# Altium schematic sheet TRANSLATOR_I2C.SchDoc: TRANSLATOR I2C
size A4; Author: Silvio Navaretti; CompanyName: ARDUINO SRL; DrawnBy: Silvio Navaretti; Engineer: Silvio Navaretti; Organization: ARDUINO SRL; DocumentNumber: ASX00083; SheetNumber: 4; SheetTotal: 11; RevAuthor: Silvio Navaretti
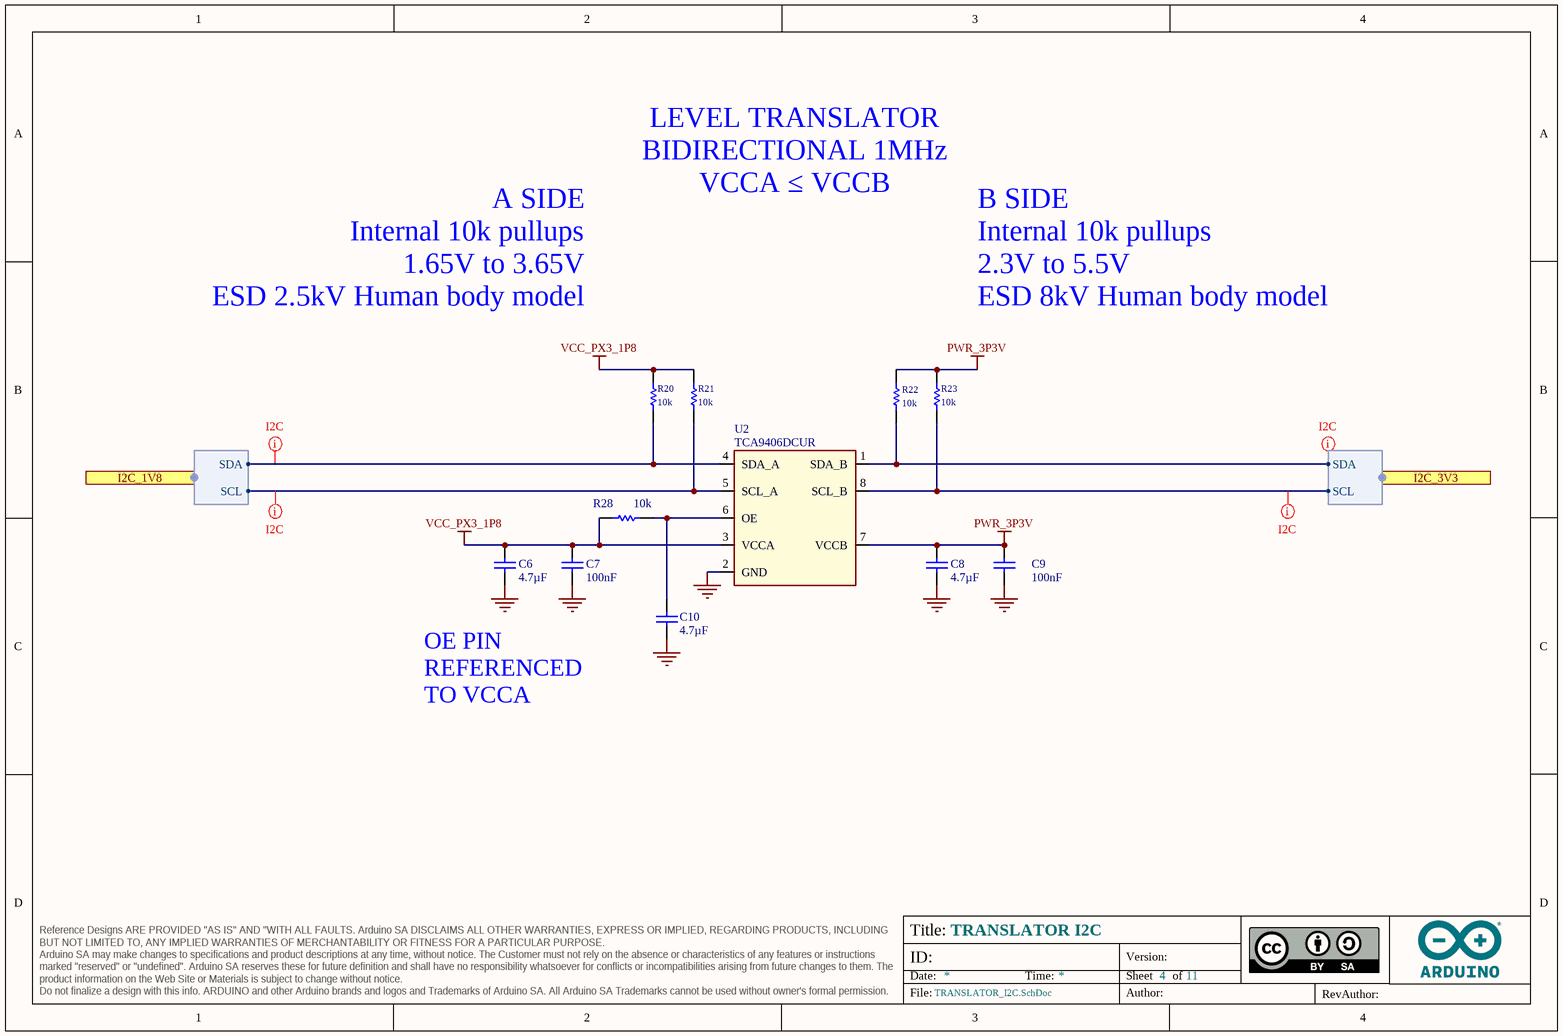
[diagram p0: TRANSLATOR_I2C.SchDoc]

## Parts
C6  value 4.7µF  [CAP-0402]  (hidden comment: C1005A475M6R3NT)
C7  value 100nF  [CAP-0402]  (hidden comment: GRM155R61H104KE19D)
C8  value 4.7µF  [CAP-0402]  (hidden comment: C1005A475M6R3NT)
C9  value 100nF  [CAP-0402]  (hidden comment: GRM155R61H104KE19D)
C10  value 4.7µF  [CAP-0402]  (hidden comment: C1005A475M6R3NT)
R20  value 10k  [RES-0402]  (hidden comment: CRCW040210K0FKED)
R21  value 10k  [RES-0402]  (hidden comment: CRCW040210K0FKED)
R22  value 10k  [RES-0402]  (hidden comment: CRCW040210K0FKED)
R23  value 10k  [RES-0402]  (hidden comment: CRCW040210K0FKED)
R28  value 10k  [RES-0402]  (hidden comment: CRCW040210K0FKED)
U2  TCA9406DCUR  [VSSOP8 pitch 0.5mm body 3.1x2x0.9mm]

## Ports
I2C_1V8 (harness I2C), I2C_3V3 (harness I2C)

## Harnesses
I2C: SDA, SCL

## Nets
GND: C6.1 C7.2 C8.1 C9.2 C10.1 U2.2(GND)
PWR_3P3V: C8.2 C9.1 R22.2 R23.2 U2.7(VCCB)
VCC_PX3_1P8: C6.2 C7.1 R20.2 R21.2 R28.2 U2.3(VCCA)
NetC10_2: C10.2 R28.1 U2.6(OE)
NetR20_1: R20.1 U2.4(SDA_A) ; port I2C_1V8.SDA
NetR21_1: R21.1 U2.5(SCL_A) ; port I2C_1V8.SCL
NetR22_1: R22.1 U2.1(SDA_B) ; port I2C_3V3.SDA
NetR23_1: R23.1 U2.8(SCL_B) ; port I2C_3V3.SCL

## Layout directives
net class I2C: NetR20_1, NetR21_1, NetR22_1, NetR23_1

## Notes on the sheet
- LEVEL TRANSLATOR
  BIDIRECTIONAL 1MHz
  VCCA ≤ VCCB
- A SIDE
  Internal 10k pullups
  1.65V to 3.65V
  ESD 2.5kV Human body model
- B SIDE
  Internal 10k pullups
  2.3V to 5.5V
  ESD 8kV Human body model
- OE PIN REFERENCED TO VCCA

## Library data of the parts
C6 C8 C10 = C0037-A.14: CAP CHIP 0402 4.7uF 20% 6V3 X5R; Manufacturer: Hottech; Code Arduino: 0833; Voltage: 6.3V
C7 C9 = C0015-A.14: CAP CHIP 0402 100nF 10% 50V X5R; Manufacturer: Murata; Code Arduino: A5141
R20-R23 R28 = R0003-A.24: RES CHIP 0402 10k 1% 1/16W; Manufacturer: Vishay; Code Arduino: 0136; Power: 62.5mW; Temperature coefficient: 100ppm
U2 = U0087-A.10: IC Translator 2b,  Push pull, OE, VCCA 1.65V to 3.6V, VCCB 2.3V to 5.5V, internal 10k pullups, Iq 2uA when VCCA or VCCB at 0V, VSSOP8 3.1x2x0.9mm; Manufacturer: Texas Instruments; Code Arduino: A5381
